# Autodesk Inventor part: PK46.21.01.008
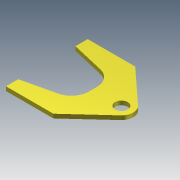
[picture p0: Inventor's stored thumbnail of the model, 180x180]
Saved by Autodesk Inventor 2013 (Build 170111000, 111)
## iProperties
Created: 2005-04
Part Number: PK46.21.01.008
Material: Steel, Mild
Document SubType Name: Modeling
Designer: salex
Manufacturer: Standard
Standards Organization: Custom
Density: 7.86 g/cm^3
Author: salex
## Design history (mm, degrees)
sketch "Эскиз1"
  geometry: L1 (-280, -40.1)-(-280, 40.1); L2 (-411.371, 205.653)-(-730, 280); L3 (-730, 280)-(-730, 400); L4 (-730, 400)-(-265, 400); L5 (-265, 400)-(77.853, 84.64); L6 (0, 0)-(-506.787, 0); L7 (-730, -400)-(-265, -400); L8 (-730, -280)-(-730, -400); L9 (-411.371, -205.653)-(-730, -280); L10 (-265, -400)-(77.853, -84.64); L11 (-411.371, 205.653)-(-280, 175); L12 (-280, 175)-(-280, 40.1); C1 r 62.5 at (0, 0); A1 r 115 centre (0, 0) between (77.853, -84.64) and (77.853, 84.64); A2 r 170 centre (-450, 40.1) between (-280, 40.1) and (-411.371, 205.653); A3 r 170 centre (-450, -40.1) between (-411.371, -205.653) and (-280, -40.1)
  constraints: 24 end point, 7 symmetric about line, 6 point on circle, 4 centre point, 4 tangent, 3 parallel, 1 coincident, 1 collinear, 1 perpendicular, 1 vertical, 2 other
  dimensions: "d0" = 115 radius of A1; "d1" = 125 diameter of C1; "d2" = 800 distance between parallel lines of L7 L4; "d3" = 265 horizontal distance of C1.centre L4.end; "d4" = 730 distance from line of L8 C1.centre; "d5" = 120 distance of L2.end L3.end; "d6" = 170 radius of A2; "d7" = 280 distance from line of C1.centre L1; "d8" = 225 distance from line of L11.end L4
extrude "Выдавливание1" new body sketch "Эскиз1" distance "d9" = 40; taper "d10" = 0 deg
body "Solid1"
